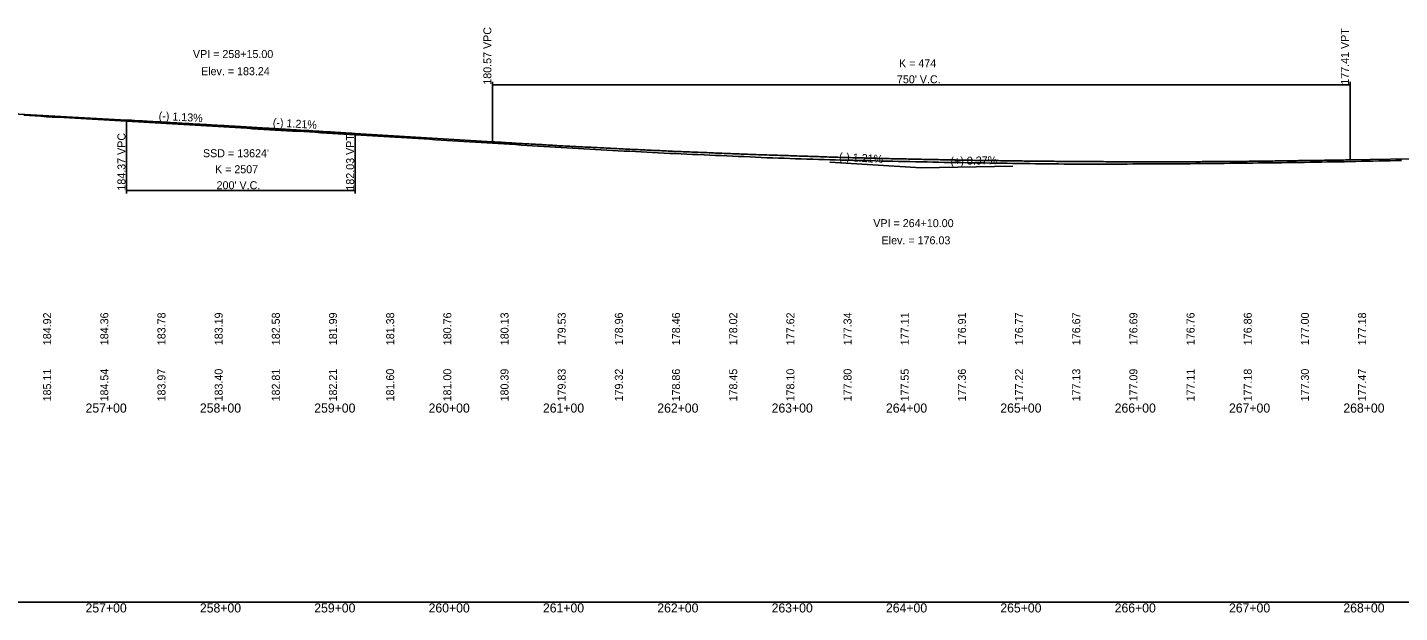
# Model space of a CAD drawing. Extents: x 1838386 to 1955906, y 719739 to 834437.
# Drawn here: x 1902991 to 1904191, y 823083 to 823595 of the extents above; entities that cross this region are included whole.
import ezdxf

# ---------------------------------------------------------------- set-up
doc = ezdxf.new("R2010")
doc.units = 0
for name, color, linetype in [('RD_DDB_GradeTX', 7, 'Continuous'), ('RD_DDB_Profile_EX', 7, 'Continuous'), ('RD_DDB_Profile_Lbl', 7, 'Continuous'), ('RD_DDB_Profile_PR', 7, 'Continuous'), ('RD_DDB_StaTX', 7, 'Continuous'), ('RD_DDB_StripGrade', 7, 'Continuous'), ('RD_DDB_VCLbl', 7, 'Continuous'), ('RD_GPK_Profile_Cell', 7, 'Continuous')]:
    doc.layers.add(name, color=color, linetype=linetype)

msp = doc.modelspace()

# ---------------------------------------------------------------- linework, layer by layer
at = {"layer": 'RD_DDB_GradeTX'}
for p, q in [((1903098.2, 823512.3), (1903178.1, 823507.8)), ((1903257.9, 823503), (1903178.1, 823507.8)), ((1903693.2, 823476.6), (1903773.1, 823471.8)), ((1903853.1, 823473.2), (1903773.1, 823471.8))]:
    msp.add_line(p, q, dxfattribs=at)
at = {"layer": 'RD_DDB_Profile_EX'}
for points in [[(1902988.1, 823517.7), (1902993.1, 823517.4), (1902998.1, 823517.1), (1903003.1, 823516.8), (1903008.1, 823516.5), (1903013.1, 823516.2), (1903018.1, 823516), (1903023.1, 823515.7), (1903028.1, 823515.4), (1903033.1, 823515.1), (1903038.1, 823514.9), (1903043.1, 823514.6), (1903048.1, 823514.3), (1903053.1, 823514), (1903058.1, 823513.7), (1903063.1, 823513.4), (1903068.1, 823513.1), (1903073.1, 823512.8), (1903078.1, 823512.6), (1903083.1, 823512.3), (1903088.1, 823512), (1903093.1, 823511.7), (1903098.1, 823511.4), (1903103.1, 823511.1), (1903108.1, 823510.8), (1903113.1, 823510.5), (1903118.1, 823510.2), (1903123.1, 823509.9), (1903128.1, 823509.6), (1903133.1, 823509.3), (1903138.1, 823509.1), (1903143.1, 823508.8), (1903148.1, 823508.5), (1903153.1, 823508.2), (1903158.1, 823507.9)], [(1903158.1, 823507.9), (1903163.1, 823507.6), (1903168.1, 823507.3), (1903173.1, 823507), (1903178.1, 823506.7), (1903183.1, 823506.4), (1903188.1, 823506), (1903193.1, 823505.7), (1903198.1, 823505.4), (1903203.1, 823505.1), (1903208.1, 823504.8), (1903213.1, 823504.5), (1903218.1, 823504.2), (1903223.1, 823503.9), (1903228.1, 823503.7), (1903233.1, 823503.4), (1903238.1, 823503.1), (1903243.1, 823502.8), (1903248.1, 823502.5), (1903253.1, 823502.2), (1903258.1, 823501.9), (1903263.1, 823501.6), (1903268.1, 823501.3), (1903273.1, 823501), (1903278.1, 823500.7), (1903283.1, 823500.4), (1903288.1, 823500.1), (1903293.1, 823499.8), (1903298.1, 823499.4), (1903303.1, 823499.1), (1903308.1, 823498.8), (1903313.1, 823498.5), (1903318.1, 823498.2), (1903323.1, 823497.9), (1903328.1, 823497.6), (1903333.1, 823497.3), (1903338.1, 823497), (1903343.1, 823496.7), (1903348.1, 823496.3), (1903353.1, 823496), (1903358.1, 823495.7), (1903363.1, 823495.4), (1903368.1, 823495.1), (1903373.1, 823494.8), (1903378.1, 823494.5), (1903383.1, 823494.2), (1903388.1, 823493.8), (1903393.1, 823493.5), (1903398.1, 823493.2), (1903403.1, 823492.9), (1903408.1, 823492.6), (1903413.1, 823492.3), (1903418.1, 823492), (1903423.1, 823491.7), (1903428.1, 823491.4), (1903433.1, 823491.1), (1903438.1, 823490.8), (1903443.1, 823490.5), (1903448.1, 823490.2), (1903453.1, 823489.9), (1903458.1, 823489.6), (1903463.1, 823489.3), (1903468.1, 823489), (1903473.1, 823488.7), (1903478.1, 823488.4), (1903483.1, 823488.1), (1903488.1, 823487.9), (1903493.1, 823487.6), (1903498.1, 823487.3), (1903503.1, 823487), (1903508.1, 823486.7), (1903513.1, 823486.4), (1903518.1, 823486.2), (1903523.1, 823485.9), (1903528.1, 823485.7), (1903533.1, 823485.4), (1903538.1, 823485.2), (1903543.1, 823484.9), (1903548.1, 823484.6), (1903553.1, 823484.4), (1903558.1, 823484.2), (1903563.1, 823483.9), (1903568.1, 823483.7), (1903573.1, 823483.5), (1903578.1, 823483.3), (1903583.1, 823483), (1903588.1, 823482.8), (1903593.1, 823482.6), (1903598.1, 823482.4), (1903603.1, 823482.2), (1903608.1, 823481.9), (1903613.1, 823481.7), (1903618.1, 823481.5), (1903623.1, 823481.3), (1903628.1, 823481.1), (1903633.1, 823480.9), (1903638.1, 823480.6), (1903643.1, 823480.4), (1903648.1, 823480.2), (1903653.1, 823480.1), (1903658.1, 823479.9)], [(1903658.1, 823479.9), (1903663.1, 823479.7), (1903668.1, 823479.5), (1903673.1, 823479.4), (1903678.1, 823479.2), (1903683.1, 823479.1), (1903688.1, 823478.9), (1903693.1, 823478.8), (1903698.1, 823478.7), (1903703.1, 823478.5), (1903708.1, 823478.4), (1903713.1, 823478.3), (1903718.1, 823478.2), (1903723.1, 823478.1), (1903728.1, 823478), (1903733.1, 823477.8), (1903738.1, 823477.7), (1903743.1, 823477.6), (1903748.1, 823477.5), (1903753.1, 823477.4), (1903758.1, 823477.3), (1903763.1, 823477.2), (1903768.1, 823477.1), (1903773.1, 823476.9), (1903778.1, 823476.9), (1903783.1, 823476.7), (1903788.1, 823476.6), (1903793.1, 823476.5), (1903798.1, 823476.4), (1903803.1, 823476.4), (1903808.1, 823476.3), (1903813.1, 823476.2), (1903818.1, 823476.1), (1903823.1, 823476), (1903828.1, 823476), (1903833.1, 823475.9), (1903838.1, 823475.8), (1903843.1, 823475.8), (1903848.1, 823475.7), (1903853.1, 823475.6), (1903858.1, 823475.6), (1903863.1, 823475.5), (1903868.1, 823475.4), (1903873.1, 823475.3), (1903878.1, 823475.3), (1903883.1, 823475.2), (1903888.1, 823475.1), (1903893.1, 823475.1), (1903898.1, 823475), (1903903.1, 823475), (1903908.1, 823475), (1903913.1, 823475), (1903918.1, 823475), (1903923.1, 823475), (1903928.1, 823475), (1903933.1, 823475), (1903938.1, 823475), (1903943.1, 823475), (1903948.1, 823475), (1903953.1, 823475), (1903958.1, 823475.1), (1903963.1, 823475.1), (1903968.1, 823475.1), (1903973.1, 823475.1), (1903978.1, 823475.1), (1903983.1, 823475.1), (1903988.1, 823475.2), (1903993.1, 823475.2), (1903998.1, 823475.3), (1904003.1, 823475.3), (1904008.1, 823475.3), (1904013.1, 823475.4), (1904018.1, 823475.4), (1904023.1, 823475.5), (1904028.1, 823475.5), (1904033.1, 823475.6), (1904038.1, 823475.6), (1904043.1, 823475.7), (1904048.1, 823475.7), (1904053.1, 823475.8), (1904058.1, 823475.8), (1904063.1, 823475.9), (1904068.1, 823476), (1904073.1, 823476), (1904078.1, 823476.1), (1904083.1, 823476.2), (1904088.1, 823476.2), (1904093.1, 823476.3), (1904098.1, 823476.4), (1904103.1, 823476.4), (1904108.1, 823476.5), (1904113.1, 823476.6), (1904118.1, 823476.7), (1904123.1, 823476.8), (1904128.1, 823476.9), (1904133.1, 823477), (1904138.1, 823477.1), (1904143.1, 823477.1), (1904148.1, 823477.2), (1904153.1, 823477.4), (1904158.1, 823477.5)], [(1904158.1, 823477.5), (1904163.1, 823477.5), (1904168.1, 823477.7), (1904173.1, 823477.8), (1904178.1, 823477.8), (1904183.1, 823477.9), (1904188.1, 823478), (1904193.1, 823478)]]:
    msp.add_lwpolyline(points, dxfattribs=at)
at = {"layer": 'RD_DDB_Profile_PR'}
for p, q in [((1902968.1, 823519.7), (1903078.1, 823513.5)), ((1903278.1, 823501.8), (1903398.1, 823494.5)), ((1904148.1, 823478.7), (1904892.3, 823492.4))]:
    msp.add_line(p, q, dxfattribs=at)
for points in [[(1903078.1, 823513.5), (1903082.1, 823513.3), (1903086.1, 823513), (1903090.1, 823512.8), (1903094.1, 823512.6), (1903098.1, 823512.3), (1903102.1, 823512.1), (1903106.1, 823511.9), (1903110.1, 823511.7), (1903114.1, 823511.4), (1903118.1, 823511.2), (1903122.1, 823511), (1903126.1, 823510.7), (1903130.1, 823510.5), (1903134.1, 823510.3), (1903138.1, 823510), (1903142.1, 823509.8), (1903146.1, 823509.6), (1903150.1, 823509.4), (1903154.1, 823509.1), (1903158.1, 823508.9), (1903162.1, 823508.7), (1903166.1, 823508.4), (1903170.1, 823508.2), (1903174.1, 823508), (1903178.1, 823507.7), (1903182.1, 823507.5), (1903186.1, 823507.3), (1903190.1, 823507), (1903194.1, 823506.8), (1903198.1, 823506.5), (1903202.1, 823506.3), (1903206.1, 823506.1), (1903210.1, 823505.8), (1903214.1, 823505.6), (1903218.1, 823505.4), (1903222.1, 823505.1), (1903226.1, 823504.9), (1903230.1, 823504.6), (1903234.1, 823504.4), (1903238.1, 823504.2), (1903242.1, 823503.9), (1903246.1, 823503.7), (1903250.1, 823503.4), (1903254.1, 823503.2), (1903258.1, 823503), (1903262.1, 823502.7), (1903266.1, 823502.5), (1903270.1, 823502.2), (1903274.1, 823502), (1903278.1, 823501.8)], [(1903398.1, 823494.5), (1903413.1, 823493.6), (1903428.1, 823492.7), (1903443.1, 823491.9), (1903458.1, 823491), (1903473.1, 823490.2), (1903488.1, 823489.5), (1903503.1, 823488.7), (1903518.1, 823488), (1903533.1, 823487.3), (1903548.1, 823486.6), (1903563.1, 823485.9), (1903578.1, 823485.3), (1903593.1, 823484.7), (1903608.1, 823484.1), (1903623.1, 823483.5), (1903638.1, 823483), (1903653.1, 823482.5), (1903668.1, 823482), (1903683.1, 823481.5), (1903698.1, 823481), (1903713.1, 823480.6), (1903728.1, 823480.2), (1903743.1, 823479.8), (1903758.1, 823479.5), (1903773.1, 823479.2), (1903788.1, 823478.9), (1903803.1, 823478.6), (1903818.1, 823478.3), (1903833.1, 823478.1), (1903848.1, 823477.9), (1903863.1, 823477.7), (1903878.1, 823477.5), (1903893.1, 823477.4), (1903908.1, 823477.3), (1903923.1, 823477.2), (1903938.1, 823477.1), (1903953.1, 823477.1), (1903968.1, 823477.1), (1903983.1, 823477.1), (1903998.1, 823477.1), (1904013.1, 823477.1), (1904028.1, 823477.2), (1904043.1, 823477.3), (1904058.1, 823477.4), (1904073.1, 823477.6), (1904088.1, 823477.8), (1904103.1, 823478), (1904118.1, 823478.2), (1904133.1, 823478.4), (1904148.1, 823478.7)]]:
    msp.add_spline(points, degree=3, dxfattribs=at)
at = {"layer": 'RD_DDB_VCLbl'}
for p, q in [((1903398.1, 823547), (1903398.1, 823494.5)), ((1903398.1, 823544.5), (1904148.1, 823544.5)), ((1904148.1, 823547), (1904148.1, 823478.7)), ((1903078.1, 823449.3), (1903078.1, 823513.5)), ((1903278.1, 823449.3), (1903278.1, 823501.8)), ((1903078.1, 823451.8), (1903278.1, 823451.8))]:
    msp.add_line(p, q, dxfattribs=at)
at = {"layer": 'RD_GPK_Profile_Cell'}
msp.add_line((1878363.1, 823091.6), (1904963.1, 823091.6), dxfattribs=at)

# ---------------------------------------------------------------- texts
at = {"layer": 'RD_DDB_GradeTX'}
for s, rotation, p in [('(-) 1.13%', 356.7587, (1903106, 823513.9)), ('(-) 1.21%', 356.5309, (1903205.8, 823508.1)), ('(-) 1.21%', 356.5309, (1903701, 823478.1)), ('(+) 0.37%', 1.0594, (1903798.7, 823474.2))]:
    msp.add_text(s, height=7, rotation=rotation, dxfattribs=at).set_placement(p)
at = {"layer": 'RD_DDB_Profile_Lbl'}
for s, p in [('VPI = 258+15.00', (1903136.1, 823567.8)), ('Elev. = 183.24', (1903143.2, 823552.8)), ('VPI = 264+10.00', (1903731.1, 823419.8)), ('Elev. = 176.03', (1903738.4, 823404.8))]:
    msp.add_text(s, height=7, dxfattribs=at).set_placement(p)
at = {"layer": 'RD_DDB_StaTX'}
for s, p in [('257+00', (1903042.2, 823257.5)), ('258+00', (1903142.2, 823257.5)), ('259+00', (1903242.2, 823257.5)), ('260+00', (1903342.2, 823257.5)), ('261+00', (1903442.2, 823257.5)), ('262+00', (1903542.2, 823257.5)), ('263+00', (1903642.2, 823257.5)), ('264+00', (1903742.2, 823257.5)), ('265+00', (1903842.2, 823257.5)), ('266+00', (1903942.2, 823257.5)), ('267+00', (1904042.2, 823257.5)), ('268+00', (1904142.2, 823257.5)), ('257+00', (1903042.2, 823082.6)), ('258+00', (1903142.2, 823082.6)), ('259+00', (1903242.2, 823082.6)), ('260+00', (1903342.2, 823082.6)), ('261+00', (1903442.2, 823082.6)), ('262+00', (1903542.2, 823082.6)), ('263+00', (1903642.2, 823082.6)), ('264+00', (1903742.2, 823082.6)), ('265+00', (1903842.2, 823082.6)), ('266+00', (1903942.2, 823082.6)), ('267+00', (1904042.2, 823082.6)), ('268+00', (1904142.2, 823082.6))]:
    msp.add_text(s, height=8, dxfattribs=at).set_placement(p)
at = {"layer": 'RD_DDB_StripGrade'}
for s, p in [('180.57 VPC', (1903397.1, 823544.5)), ('177.41 VPT', (1904147.1, 823544.5)), ('184.37 VPC', (1903077.1, 823451.8)), ('182.03 VPT', (1903277.1, 823451.8)), ('184.92', (1903012.1, 823316.5)), ('184.36', (1903062.1, 823316.5)), ('183.78', (1903112.1, 823316.5)), ('183.19', (1903162.1, 823316.5)), ('182.58', (1903212.1, 823316.5)), ('181.99', (1903262.1, 823316.5)), ('181.38', (1903312.1, 823316.5)), ('180.76', (1903362.1, 823316.5)), ('180.13', (1903412.1, 823316.5)), ('179.53', (1903462.1, 823316.5)), ('178.96', (1903512.1, 823316.5)), ('178.46', (1903562.1, 823316.5)), ('178.02', (1903612.1, 823316.5)), ('177.62', (1903662.1, 823316.5)), ('177.34', (1903712.1, 823316.5)), ('177.11', (1903762.1, 823316.5)), ('176.91', (1903812.1, 823316.5)), ('176.77', (1903862.1, 823316.5)), ('176.67', (1903912.1, 823316.5)), ('176.69', (1903962.1, 823316.5)), ('176.76', (1904012.1, 823316.5)), ('176.86', (1904062.1, 823316.5)), ('177.00', (1904112.1, 823316.5)), ('177.18', (1904162.1, 823316.5)), ('185.11', (1903012.1, 823267.3)), ('184.54', (1903062.1, 823267.3)), ('183.97', (1903112.1, 823267.3)), ('183.40', (1903162.1, 823267.3)), ('182.81', (1903212.1, 823267.3)), ('182.21', (1903262.1, 823267.3)), ('181.60', (1903312.1, 823267.3)), ('181.00', (1903362.1, 823267.3)), ('180.39', (1903412.1, 823267.3)), ('179.83', (1903462.1, 823267.3)), ('179.32', (1903512.1, 823267.3)), ('178.86', (1903562.1, 823267.3)), ('178.45', (1903612.1, 823267.3)), ('178.10', (1903662.1, 823267.3)), ('177.80', (1903712.1, 823267.3)), ('177.55', (1903762.1, 823267.3)), ('177.36', (1903812.1, 823267.3)), ('177.22', (1903862.1, 823267.3)), ('177.13', (1903912.1, 823267.3)), ('177.09', (1903962.1, 823267.3)), ('177.11', (1904012.1, 823267.3)), ('177.18', (1904062.1, 823267.3)), ('177.30', (1904112.1, 823267.3)), ('177.47', (1904162.1, 823267.3))]:
    msp.add_text(s, height=7, rotation=90, dxfattribs=at).set_placement(p)
at = {"layer": 'RD_DDB_VCLbl'}
for s, p in [('K = 474', (1903753.6, 823559.7)), ("750' V.C.", (1903751.8, 823545.7)), ("SSD = 13624'", (1903144.9, 823481)), ('K = 2507', (1903155.4, 823467)), ("200' V.C.", (1903156.8, 823453))]:
    msp.add_text(s, height=7, dxfattribs=at).set_placement(p)

doc.saveas('drawing.dxf')
